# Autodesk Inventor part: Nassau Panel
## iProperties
Shininess: 20.0
Angle Display Precision: 2
Document Length Units: 11269
Document Angle Units: 11279
Document Time Units: 11290
Document Mass Units: 11283
Document Length Units Precision: 3
Document Angle Units Precision: 2
Compacted: True
Created: 2001-08
Part Number: Nassau Panel
Document SubType Name: Modeling
Designer: Martin Budgell
Density: 0.0
Volumn: 0.0
Area: 0.0
PropertySet Name: Model Information
Control State: 0
Master: False
Checked Out: False
Author: Martin Budgell
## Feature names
1. Loft1
2. Extrusion8
3. Fillet5
4. Shell1
5. Fillet6
6. Extrusion9
7. Fillet7
8. Hole1
